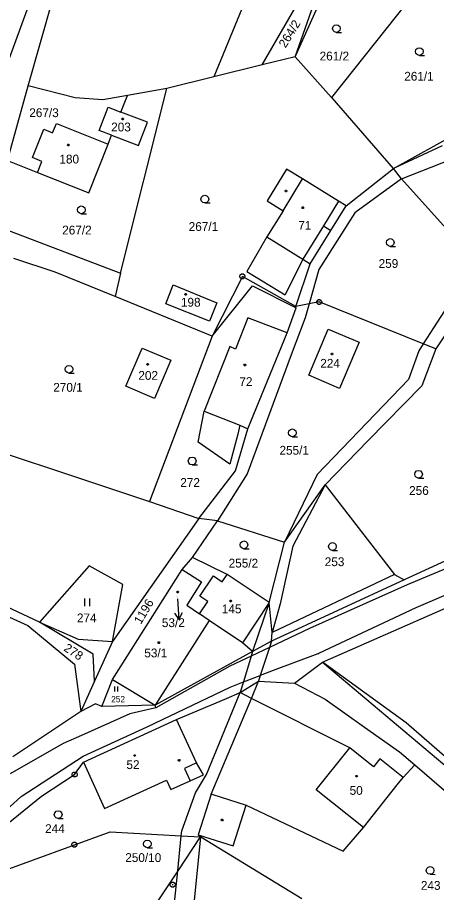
# Model space of a CAD drawing. Extents: x -694465 to -690527, y -983694 to -978978.
# Drawn here: x -692355.9 to -692275, y -981773.5 to -981604.7 of the extents above; entities that cross this region are included whole.
import ezdxf

# ---------------------------------------------------------------- set-up
doc = ezdxf.new("R2010")
doc.units = 0
for name, color, linetype in [('Vrstva 1', 7, 'Continuous'), ('Vrstva 16', 7, 'Continuous'), ('Vrstva 18', 7, 'Continuous'), ('Vrstva 19', 7, 'Continuous'), ('Vrstva 24', 7, 'Continuous'), ('Vrstva 25', 7, 'Continuous'), ('Vrstva 29', 7, 'Continuous')]:
    doc.layers.add(name, color=color, linetype=linetype)

msp = doc.modelspace()

# ---------------------------------------------------------------- linework, layer by layer
at = {"layer": 'Vrstva 1'}
for p, q in [((-692299.625, -981673.727), (-692295.881, -981664.883)), ((-692295.881, -981664.883), (-692289.89, -981667.368)), ((-692289.89, -981667.368), (-692293.694, -981676.29)), ((-692293.694, -981676.29), (-692299.625, -981673.727))]:
    msp.add_line(p, q, dxfattribs=at)
for points in [[(-692307.62, -981590.99), (-692317.93, -981616.19)], [(-692350.11, -981592.51), (-692357.7, -981613.37)], [(-692308.61, -981613.86), (-692298.36, -981596.04)], [(-692302.26, -981612.28), (-692296.79, -981596.72)], [(-692276.27, -981596.23), (-692295.22, -981620.14)], [(-692302.26, -981612.28), (-692297, -981600.55)], [(-692353.77, -981617.9), (-692349.04, -981601.09)], [(-692302.26, -981612.28), (-692308.61, -981613.86)], [(-692295.22, -981620.14), (-692302.26, -981612.28)], [(-692308.61, -981613.86), (-692317.93, -981616.19)], [(-692317.93, -981616.19), (-692327.01, -981618.45)], [(-692357.81, -981632.33), (-692353.77, -981617.9)], [(-692344.71, -981620.23), (-692353.77, -981617.9)], [(-692335.95, -981654.07), (-692327.01, -981618.45)], [(-692327.01, -981618.45), (-692334.63, -981619.78)], [(-692339.36, -981620.61), (-692344.71, -981620.23)], [(-692334.63, -981619.78), (-692339.36, -981620.61)], [(-692335.9, -981622.96), (-692334.63, -981619.78)], [(-692295.12, -981620.24), (-692295.22, -981620.14)], [(-692283.26, -981633.84), (-692295.12, -981620.24)], [(-692340.06, -981626.53), (-692338.34, -981622.02)], [(-692338.34, -981622.02), (-692335.9, -981622.96)], [(-692330.78, -981624.92), (-692335.9, -981622.96)], [(-692349.07, -981626.97), (-692348.35, -981625.19)], [(-692348.35, -981625.19), (-692338.36, -981629.18)], [(-692332.49, -981629.43), (-692330.78, -981624.92)], [(-692352.97, -981631.75), (-692350.78, -981626.28)], [(-692350.78, -981626.28), (-692349.07, -981626.97)], [(-692337.68, -981627.44), (-692340.06, -981626.53)], [(-692338.36, -981629.18), (-692337.68, -981627.44)], [(-692337.68, -981627.44), (-692332.49, -981629.43)], [(-692283.26, -981633.84), (-692270.72, -981626.88)], [(-692342.1, -981638.55), (-692338.36, -981629.18)], [(-692273.88, -981629.46), (-692283.26, -981633.84)], [(-692357.81, -981632.33), (-692351.99, -981634.6)], [(-692351.14, -981632.48), (-692352.97, -981631.75)], [(-692351.99, -981634.6), (-692351.14, -981632.48)], [(-692281.72, -981635.87), (-692272.06, -981632.07)], [(-692351.99, -981634.6), (-692342.1, -981638.55)], [(-692303.9, -981633.95), (-692307.69, -981640.07)], [(-692300.86, -981635.83), (-692303.9, -981633.95)], [(-692292.43, -981641.05), (-692283.26, -981633.84)], [(-692281.72, -981635.87), (-692283.26, -981633.84)], [(-692304.59, -981641.99), (-692300.86, -981635.83)], [(-692293.87, -981640.16), (-692300.86, -981635.83)], [(-692281.72, -981635.87), (-692290.756, -981642.38), (-692297.668, -981653.309), (-692299.571, -981659.973)], [(-692267.3, -981651.89), (-692281.72, -981635.87)], [(-692307.69, -981640.07), (-692304.59, -981641.99)], [(-692293.87, -981640.16), (-692296.81, -981644.9)], [(-692295.36, -981645.79), (-692292.43, -981641.05)], [(-692292.43, -981641.05), (-692293.87, -981640.16)], [(-692304.59, -981641.99), (-692307.73, -981647.06)], [(-692361.21, -981644.47), (-692335.95, -981654.07)], [(-692296.81, -981644.9), (-692300.8, -981651.35)], [(-692299.36, -981652.25), (-692295.36, -981645.79)], [(-692296.81, -981644.9), (-692295.36, -981645.79)], [(-692307.73, -981647.06), (-692311.56, -981653.7)], [(-692307.73, -981647.06), (-692300.8, -981651.35)], [(-692348.56, -981653.87), (-692356.56, -981651.21)], [(-692300.8, -981651.35), (-692304.18, -981658.24)], [(-692300.8, -981651.35), (-692299.36, -981652.25)], [(-692302.1, -981660.47), (-692299.36, -981652.25)], [(-692267.3, -981651.89), (-692277.538, -981667.685)], [(-692336.988, -981658.569), (-692348.56, -981653.87)], [(-692335.95, -981654.07), (-692336.988, -981658.569)], [(-692312.44, -981654.68), (-692318.27, -981666.17)], [(-692302.1, -981660.47), (-692312.44, -981654.68)], [(-692311.56, -981653.7), (-692304.18, -981658.24)], [(-692317.37, -981659.78), (-692318.82, -981663.28), (-692327.25, -981659.96), (-692325.79, -981656.29), (-692317.37, -981659.78)], [(-692318.27, -981666.17), (-692310.52, -981656.5)], [(-692310.52, -981656.5), (-692302.03, -981660.75)], [(-692267.89, -981657.86), (-692275.12, -981668.66)], [(-692318.27, -981666.17), (-692336.988, -981658.569)], [(-692297.62, -981659.59), (-692299.571, -981659.973)], [(-692277.538, -981667.685), (-692297.62, -981659.59)], [(-692299.571, -981659.973), (-692300.343, -981662.678), (-692303.019, -981669.816), (-692311.491, -981692.791), (-692317.25, -981701.8)], [(-692303.82, -981665.56), (-692302.03, -981660.75)], [(-692299.571, -981659.973), (-692302.1, -981660.47)], [(-692302.03, -981660.75), (-692302.1, -981660.47)], [(-692311.4, -981662.69), (-692313.75, -981668.74)], [(-692303.82, -981665.56), (-692311.4, -981662.69)], [(-692318.27, -981666.17), (-692330.39, -981698.13)], [(-692311.38, -981684.08), (-692303.82, -981665.56)], [(-692314.85, -981668.22), (-692319.83, -981680.69)], [(-692313.75, -981668.74), (-692314.85, -981668.22)], [(-692277.538, -981667.685), (-692278.399, -981669.014), (-692280.406, -981674.59), (-692298.019, -981692.881), (-692304.31, -981705.93)], [(-692275.12, -981668.66), (-692277.538, -981667.685)], [(-692326.27, -981670.84), (-692329.39, -981678.21), (-692334.92, -981675.87), (-692331.8, -981668.5), (-692326.27, -981670.84)], [(-692275.12, -981668.66), (-692277.83, -981675.76)], [(-692277.83, -981675.76), (-692288.19, -981686.34)], [(-692320.98, -981686.62), (-692319.83, -981680.69)], [(-692319.83, -981680.69), (-692312.93, -981683.4)], [(-692374.11, -981683.55), (-692330.39, -981698.13)], [(-692312.93, -981683.4), (-692313.32, -981685.08)], [(-692312.93, -981683.4), (-692311.38, -981684.08)], [(-692313.32, -981685.08), (-692314.86, -981690.9)], [(-692313.75, -981692.18), (-692311.38, -981684.08)], [(-692314.86, -981690.9), (-692320.98, -981686.62)], [(-692288.19, -981686.34), (-692296.45, -981694.86)], [(-692320.83, -981701.38), (-692313.75, -981692.18)], [(-692296.45, -981694.86), (-692302.701, -981706.71), (-692305.154, -981717.863)], [(-692304.31, -981705.93), (-692296.45, -981694.86)], [(-692296.45, -981694.86), (-692283.08, -981712.2)], [(-692231.78, -981693.79), (-692280.66, -981714.19)], [(-692330.39, -981698.13), (-692320.83, -981701.38)], [(-692278.89, -981718.56), (-692230.3, -981697.74)], [(-692250.23, -981699), (-692281.2, -981713.23)], [(-692320.83, -981701.38), (-692337.53, -981725.12)], [(-692322.09, -981708.9), (-692317.25, -981701.8)], [(-692317.25, -981701.8), (-692320.83, -981701.38)], [(-692317.25, -981701.8), (-692304.31, -981705.93)], [(-692351.63, -981721.39), (-692384.16, -981706.16)], [(-692307.26, -981717.6), (-692304.31, -981705.93)], [(-692385.08, -981707.85), (-692353.84, -981722.03)], [(-692342.03, -981710.53), (-692351.63, -981721.39)], [(-692335.54, -981714.12), (-692342.03, -981710.53)], [(-692324.1, -981711.25), (-692322.09, -981708.9)], [(-692315.41, -981712.16), (-692322.09, -981708.9)], [(-692337.49, -981732.41), (-692324.1, -981711.25)], [(-692324.1, -981711.25), (-692320.34, -981713.6)], [(-692316.36, -981713.59), (-692315.41, -981712.16)], [(-692307.26, -981717.6), (-692315.41, -981712.16)], [(-692283.08, -981712.2), (-692306.68, -981723.39)], [(-692296.96, -981729.07), (-692257.29, -981711.65)], [(-692283.08, -981712.2), (-692281.2, -981713.23)], [(-692320.34, -981713.6), (-692323.19, -981718.1)], [(-692320.66, -981716.39), (-692318.05, -981712.47)], [(-692318.05, -981712.47), (-692316.36, -981713.59)], [(-692281.2, -981713.23), (-692306.8, -981725.07)], [(-692337.53, -981725.12), (-692335.54, -981714.12)], [(-692280.66, -981714.19), (-692299.48, -981722.62)], [(-692319.14, -981717.41), (-692320.66, -981716.39)], [(-692323.19, -981718.1), (-692320.73, -981719.8)], [(-692320.73, -981719.8), (-692319.14, -981717.41)], [(-692307.26, -981717.6), (-692312.42, -981725.35)], [(-692307.26, -981717.6), (-692310.47, -981727.05)], [(-692306.68, -981723.39), (-692307.26, -981717.6)], [(-692305.154, -981717.863), (-692306.68, -981723.39)], [(-692297.712, -981727.382), (-692278.89, -981718.56)], [(-692318.84, -981721.06), (-692320.73, -981719.8)], [(-692353.84, -981722.03), (-692344.83, -981729.49)], [(-692341.24, -981727.58), (-692351.63, -981721.39)], [(-692351.63, -981721.39), (-692344.16, -981724.65)], [(-692318.84, -981721.06), (-692329.27, -981737.41)], [(-692312.42, -981725.35), (-692318.84, -981721.06)], [(-692299.48, -981722.62), (-692307.19, -981726.25)], [(-692306.8, -981725.07), (-692306.68, -981723.39)], [(-692344.16, -981724.65), (-692337.53, -981725.12)], [(-692337.53, -981725.12), (-692341, -981732.793)], [(-692310.47, -981727.05), (-692312.42, -981725.35)], [(-692306.8, -981725.07), (-692310.47, -981727.05)], [(-692306.8, -981725.07), (-692307.19, -981726.25)], [(-692310.47, -981727.05), (-692329.27, -981737.41)], [(-692307.19, -981726.25), (-692310.74, -981727.92)], [(-692310.47, -981727.05), (-692310.74, -981727.92)], [(-692307.19, -981726.25), (-692308.99, -981731.67)], [(-692297.9, -981727.47), (-692297.712, -981727.382)], [(-692341, -981732.793), (-692341.24, -981727.58)], [(-692310.74, -981727.92), (-692314.85, -981729.86)], [(-692310.74, -981727.92), (-692312.25, -981732.91)], [(-692297.9, -981727.47), (-692306.477, -981730.718)], [(-692302.4, -981733.16), (-692296.96, -981729.07)], [(-692280.84, -981740.82), (-692296.96, -981729.07)], [(-692296.96, -981729.07), (-692262.73, -981757.9)], [(-692344.83, -981729.49), (-692343.64, -981738.63)], [(-692314.85, -981729.86), (-692329.14, -981737.9)], [(-692306.477, -981730.718), (-692308.99, -981731.67)], [(-692339.6, -981737.65), (-692337.49, -981732.41)], [(-692337.49, -981732.41), (-692329.27, -981737.41)], [(-692312.25, -981732.91), (-692308.99, -981731.67)], [(-692308.99, -981731.67), (-692309.35, -981732.74)], [(-692341, -981732.793), (-692343.64, -981738.63)], [(-692330.85, -981741.55), (-692314.82, -981733.95)], [(-692314.82, -981733.95), (-692312.25, -981732.91)], [(-692312.88, -981734.97), (-692309.35, -981732.74)], [(-692312.25, -981732.91), (-692312.85, -981734.872)], [(-692310.664, -981736.084), (-692309.35, -981732.74)], [(-692309.35, -981732.74), (-692302.4, -981733.16)], [(-692302.4, -981733.16), (-692296.44, -981736.23)], [(-692321.492, -981754.275), (-692319.349, -981750.77), (-692312.892, -981734.975)], [(-692315.519, -981736.085), (-692312.892, -981734.975)], [(-692312.892, -981734.975), (-692312.85, -981734.872)], [(-692312.892, -981734.975), (-692312.88, -981734.97)], [(-692312.85, -981734.872), (-692312.88, -981734.97)], [(-692310.664, -981736.084), (-692312.88, -981734.97)], [(-692340.8, -981737.15), (-692343.64, -981738.63)], [(-692339.6, -981737.65), (-692340.8, -981737.15)], [(-692329.27, -981737.41), (-692339.6, -981737.65)], [(-692329.14, -981737.9), (-692329.27, -981737.41)], [(-692325.14, -981740.15), (-692315.519, -981736.085)], [(-692318.49, -981754.54), (-692310.664, -981736.084)], [(-692291.72, -981745.61), (-692310.664, -981736.084)], [(-692296.44, -981736.23), (-692288.84, -981741.61)], [(-692343.64, -981738.63), (-692356.757, -981747.363)], [(-692334.2, -981739.06), (-692343.508, -981743.218)], [(-692329.14, -981737.9), (-692334.2, -981739.06)], [(-692343.14, -981748.4), (-692325.14, -981740.15)], [(-692321.29, -981748.55), (-692325.14, -981740.15)], [(-692262.05, -981757.15), (-692280.84, -981740.82)], [(-692343.21, -981747.24), (-692330.85, -981741.55)], [(-692288.84, -981741.61), (-692282.09, -981746.39)], [(-692343.508, -981743.218), (-692347.05, -981744.8)], [(-692347.05, -981744.8), (-692357.25, -981750.65)], [(-692298.19, -981753.74), (-692291.72, -981745.61)], [(-692287.13, -981749.27), (-692291.72, -981745.61)], [(-692355.16, -981755.04), (-692343.21, -981747.24)], [(-692282.09, -981746.39), (-692279.142, -981748.931)], [(-692344.83, -981750.77), (-692343.14, -981748.4)], [(-692343.14, -981748.4), (-692339.05, -981757.32)], [(-692321.29, -981748.55), (-692323.62, -981749.62)], [(-692319.97, -981750.86), (-692321.29, -981748.55)], [(-692285.93, -981747.76), (-692287.13, -981749.27)], [(-692281.41, -981751.35), (-692285.93, -981747.76)], [(-692281.41, -981751.35), (-692279.142, -981748.931)], [(-692279.142, -981748.931), (-692251.02, -981773.17)], [(-692351.21, -981754.97), (-692344.83, -981750.77)], [(-692323.62, -981749.62), (-692322.54, -981751.98)], [(-692322.54, -981751.98), (-692319.97, -981750.86)], [(-692339.05, -981757.32), (-692327.09, -981751.84)], [(-692327.09, -981751.84), (-692326.25, -981753.68)], [(-692326.25, -981753.68), (-692322.54, -981751.98)], [(-692289.09, -981760.99), (-692282.55, -981752.77)], [(-692282.55, -981752.77), (-692281.41, -981751.35)], [(-692324.244, -981762.589), (-692324.149, -981761.636), (-692321.492, -981754.275)], [(-692289.09, -981760.99), (-692298.19, -981753.74)], [(-692368.2, -981766.86), (-692355.16, -981755.04)], [(-692363.57, -981764.94), (-692351.21, -981754.97)], [(-692318.49, -981754.54), (-692320.99, -981762.38)], [(-692318.49, -981754.54), (-692318.36, -981754.581)], [(-692318.36, -981754.581), (-692311.74, -981756.69)], [(-692314.24, -981764.53), (-692311.74, -981756.69)], [(-692311.74, -981756.69), (-692293, -981765.54)], [(-692293, -981765.54), (-692289.09, -981760.99)], [(-692360.24, -981769.91), (-692337.99, -981761.8)], [(-692337.99, -981761.8), (-692324.244, -981762.589)], [(-692324.917, -981769.33), (-692324.244, -981762.589)], [(-692320.57, -981762.8), (-692324.917, -981769.33)], [(-692324.244, -981762.589), (-692320.57, -981762.8)], [(-692322.887, -981788.725), (-692323.034, -981788.549), (-692320.494, -981762.846)], [(-692320.57, -981762.8), (-692320.99, -981762.38)], [(-692320.99, -981762.38), (-692314.24, -981764.53)], [(-692320.494, -981762.846), (-692320.57, -981762.8)], [(-692300.94, -981774.75), (-692320.494, -981762.846)], [(-692324.917, -981769.33), (-692352.355, -981810.441)], [(-692326.9, -981788.4), (-692324.917, -981769.33)]]:
    msp.add_lwpolyline(points, dxfattribs=at)
at = {"layer": 'Vrstva 24'}
for points in [[(-692312.286, -981654.204), (-692312.036, -981654.386), (-692311.94, -981654.68), (-692312.036, -981654.974), (-692312.286, -981655.156), (-692312.594, -981655.156), (-692312.844, -981654.974), (-692312.94, -981654.68), (-692312.844, -981654.386), (-692312.594, -981654.204)], [(-692297.466, -981659.114), (-692297.216, -981659.296), (-692297.12, -981659.59), (-692297.216, -981659.884), (-692297.466, -981660.066), (-692297.774, -981660.066), (-692298.024, -981659.884), (-692298.12, -981659.59), (-692298.024, -981659.296), (-692297.774, -981659.114)], [(-692344.676, -981750.294), (-692344.426, -981750.476), (-692344.33, -981750.77), (-692344.426, -981751.064), (-692344.676, -981751.246), (-692344.984, -981751.246), (-692345.234, -981751.064), (-692345.33, -981750.77), (-692345.234, -981750.476), (-692344.984, -981750.294)], [(-692344.726, -981763.834), (-692344.476, -981764.016), (-692344.38, -981764.31), (-692344.476, -981764.604), (-692344.726, -981764.786), (-692345.034, -981764.786), (-692345.284, -981764.604), (-692345.38, -981764.31), (-692345.284, -981764.016), (-692345.034, -981763.834)], [(-692325.756, -981771.534), (-692325.506, -981771.716), (-692325.41, -981772.01), (-692325.506, -981772.304), (-692325.756, -981772.486), (-692326.064, -981772.486), (-692326.314, -981772.304), (-692326.41, -981772.01), (-692326.314, -981771.716), (-692326.064, -981771.534)]]:
    msp.add_lwpolyline(points, close=True, dxfattribs=at)
for points in [[(-692312.559, -981654.68), (-692312.32, -981654.68)], [(-692297.739, -981659.59), (-692297.5, -981659.59)], [(-692344.949, -981750.77), (-692344.71, -981750.77)], [(-692344.999, -981764.31), (-692344.76, -981764.31)], [(-692326.029, -981772.01), (-692325.79, -981772.01)]]:
    msp.add_lwpolyline(points, dxfattribs=at)
at = {"layer": 'Vrstva 25'}
for points in [[(-692294.3, -981607.61), (-692294.675, -981607.509), (-692294.949, -981607.235), (-692295.05, -981606.86), (-692294.949, -981606.485), (-692294.675, -981606.211), (-692294.3, -981606.11), (-692293.925, -981606.211), (-692293.651, -981606.485), (-692293.55, -981606.86), (-692293.651, -981607.235), (-692293.925, -981607.509), (-692294.3, -981607.61), (-692293.3, -981607.611)], [(-692278.28, -981612.05), (-692278.655, -981611.949), (-692278.929, -981611.675), (-692279.03, -981611.3), (-692278.929, -981610.925), (-692278.655, -981610.651), (-692278.28, -981610.55), (-692277.905, -981610.651), (-692277.631, -981610.925), (-692277.53, -981611.3), (-692277.631, -981611.675), (-692277.905, -981611.949), (-692278.28, -981612.05), (-692277.28, -981612.051)], [(-692319.69, -981640.5), (-692320.065, -981640.399), (-692320.339, -981640.125), (-692320.44, -981639.75), (-692320.339, -981639.375), (-692320.065, -981639.101), (-692319.69, -981639), (-692319.315, -981639.101), (-692319.041, -981639.375), (-692318.94, -981639.75), (-692319.041, -981640.125), (-692319.315, -981640.399), (-692319.69, -981640.5), (-692318.69, -981640.501)], [(-692343.54, -981642.58), (-692343.915, -981642.479), (-692344.189, -981642.205), (-692344.29, -981641.83), (-692344.189, -981641.455), (-692343.915, -981641.181), (-692343.54, -981641.08), (-692343.165, -981641.181), (-692342.891, -981641.455), (-692342.79, -981641.83), (-692342.891, -981642.205), (-692343.165, -981642.479), (-692343.54, -981642.58), (-692342.54, -981642.581)], [(-692283.89, -981648.87), (-692284.265, -981648.769), (-692284.539, -981648.495), (-692284.64, -981648.12), (-692284.539, -981647.745), (-692284.265, -981647.471), (-692283.89, -981647.37), (-692283.515, -981647.471), (-692283.241, -981647.745), (-692283.14, -981648.12), (-692283.241, -981648.495), (-692283.515, -981648.769), (-692283.89, -981648.87), (-692282.89, -981648.871)], [(-692345.92, -981673.34), (-692346.295, -981673.239), (-692346.569, -981672.965), (-692346.67, -981672.59), (-692346.569, -981672.215), (-692346.295, -981671.941), (-692345.92, -981671.84), (-692345.545, -981671.941), (-692345.271, -981672.215), (-692345.17, -981672.59), (-692345.271, -981672.965), (-692345.545, -981673.239), (-692345.92, -981673.34), (-692344.92, -981673.341)], [(-692302.8, -981685.6), (-692303.175, -981685.499), (-692303.449, -981685.225), (-692303.55, -981684.85), (-692303.449, -981684.475), (-692303.175, -981684.201), (-692302.8, -981684.1), (-692302.425, -981684.201), (-692302.151, -981684.475), (-692302.05, -981684.85), (-692302.151, -981685.225), (-692302.425, -981685.499), (-692302.8, -981685.6), (-692301.8, -981685.601)], [(-692322.14, -981691.03), (-692322.515, -981690.929), (-692322.789, -981690.655), (-692322.89, -981690.28), (-692322.789, -981689.905), (-692322.515, -981689.631), (-692322.14, -981689.53), (-692321.765, -981689.631), (-692321.491, -981689.905), (-692321.39, -981690.28), (-692321.491, -981690.655), (-692321.765, -981690.929), (-692322.14, -981691.03), (-692321.14, -981691.031)], [(-692278.43, -981693.6), (-692278.805, -981693.499), (-692279.079, -981693.225), (-692279.18, -981692.85), (-692279.079, -981692.475), (-692278.805, -981692.201), (-692278.43, -981692.1), (-692278.055, -981692.201), (-692277.781, -981692.475), (-692277.68, -981692.85), (-692277.781, -981693.225), (-692278.055, -981693.499), (-692278.43, -981693.6), (-692277.43, -981693.601)], [(-692312.14, -981707.22), (-692312.515, -981707.119), (-692312.789, -981706.845), (-692312.89, -981706.47), (-692312.789, -981706.095), (-692312.515, -981705.821), (-692312.14, -981705.72), (-692311.765, -981705.821), (-692311.491, -981706.095), (-692311.39, -981706.47), (-692311.491, -981706.845), (-692311.765, -981707.119), (-692312.14, -981707.22), (-692311.14, -981707.221)], [(-692295.06, -981707.54), (-692295.435, -981707.439), (-692295.709, -981707.165), (-692295.81, -981706.79), (-692295.709, -981706.415), (-692295.435, -981706.141), (-692295.06, -981706.04), (-692294.685, -981706.141), (-692294.411, -981706.415), (-692294.31, -981706.79), (-692294.411, -981707.165), (-692294.685, -981707.439), (-692295.06, -981707.54), (-692294.06, -981707.541)], [(-692342.9, -981716.82), (-692342.9, -981718.32)], [(-692341.9, -981718.32), (-692341.9, -981716.82)], [(-692337.145, -981733.775), (-692337.145, -981734.78)], [(-692336.475, -981734.78), (-692336.475, -981733.775)], [(-692348.01, -981759.26), (-692348.385, -981759.159), (-692348.659, -981758.885), (-692348.76, -981758.51), (-692348.659, -981758.135), (-692348.385, -981757.861), (-692348.01, -981757.76), (-692347.635, -981757.861), (-692347.361, -981758.135), (-692347.26, -981758.51), (-692347.361, -981758.885), (-692347.635, -981759.159), (-692348.01, -981759.26), (-692347.01, -981759.261)], [(-692330.79, -981764.92), (-692331.165, -981764.819), (-692331.439, -981764.545), (-692331.54, -981764.17), (-692331.439, -981763.795), (-692331.165, -981763.521), (-692330.79, -981763.42), (-692330.415, -981763.521), (-692330.141, -981763.795), (-692330.04, -981764.17), (-692330.141, -981764.545), (-692330.415, -981764.819), (-692330.79, -981764.92), (-692329.79, -981764.921)], [(-692276.21, -981770.03), (-692276.585, -981769.929), (-692276.859, -981769.655), (-692276.96, -981769.28), (-692276.859, -981768.905), (-692276.585, -981768.631), (-692276.21, -981768.53), (-692275.835, -981768.631), (-692275.561, -981768.905), (-692275.46, -981769.28), (-692275.561, -981769.655), (-692275.835, -981769.929), (-692276.21, -981770.03), (-692275.21, -981770.031)]]:
    msp.add_lwpolyline(points, dxfattribs=at)
for points in [[(-692335.483, -981624.158), (-692335.395, -981624.31), (-692335.483, -981624.462), (-692335.657, -981624.462), (-692335.745, -981624.31), (-692335.657, -981624.158)], [(-692345.963, -981629.188), (-692345.875, -981629.34), (-692345.963, -981629.492), (-692346.137, -981629.492), (-692346.225, -981629.34), (-692346.137, -981629.188)], [(-692303.923, -981638.028), (-692303.835, -981638.18), (-692303.923, -981638.332), (-692304.097, -981638.332), (-692304.185, -981638.18), (-692304.097, -981638.028)], [(-692300.693, -981641.248), (-692300.605, -981641.4), (-692300.693, -981641.552), (-692300.867, -981641.552), (-692300.955, -981641.4), (-692300.867, -981641.248)], [(-692323.313, -981657.958), (-692323.225, -981658.11), (-692323.313, -981658.262), (-692323.487, -981658.262), (-692323.575, -981658.11), (-692323.487, -981657.958)], [(-692295.053, -981669.468), (-692294.965, -981669.62), (-692295.053, -981669.772), (-692295.227, -981669.772), (-692295.315, -981669.62), (-692295.227, -981669.468)], [(-692330.653, -981671.468), (-692330.565, -981671.62), (-692330.653, -981671.772), (-692330.827, -981671.772), (-692330.915, -981671.62), (-692330.827, -981671.468)], [(-692311.873, -981671.628), (-692311.785, -981671.78), (-692311.873, -981671.932), (-692312.047, -981671.932), (-692312.135, -981671.78), (-692312.047, -981671.628)], [(-692324.833, -981715.408), (-692324.745, -981715.56), (-692324.833, -981715.712), (-692325.007, -981715.712), (-692325.095, -981715.56), (-692325.007, -981715.408)], [(-692314.633, -981717.158), (-692314.545, -981717.31), (-692314.633, -981717.462), (-692314.807, -981717.462), (-692314.895, -981717.31), (-692314.807, -981717.158)], [(-692328.483, -981725.198), (-692328.395, -981725.35), (-692328.483, -981725.502), (-692328.657, -981725.502), (-692328.745, -981725.35), (-692328.657, -981725.198)], [(-692333.153, -981746.958), (-692333.065, -981747.11), (-692333.153, -981747.262), (-692333.327, -981747.262), (-692333.415, -981747.11), (-692333.327, -981746.958)], [(-692324.573, -981747.888), (-692324.485, -981748.04), (-692324.573, -981748.192), (-692324.747, -981748.192), (-692324.835, -981748.04), (-692324.747, -981747.888)], [(-692290.313, -981750.938), (-692290.225, -981751.09), (-692290.313, -981751.242), (-692290.487, -981751.242), (-692290.575, -981751.09), (-692290.487, -981750.938)], [(-692316.273, -981759.378), (-692316.185, -981759.53), (-692316.273, -981759.682), (-692316.447, -981759.682), (-692316.535, -981759.53), (-692316.447, -981759.378)]]:
    msp.add_lwpolyline(points, close=True, dxfattribs=at)
at = {"layer": 'Vrstva 29'}
for points in [[(-692324.98, -981716.89), (-692324.683, -981720.879), (-692324.031, -981719.527)], [(-692325.527, -981719.638), (-692324.683, -981720.879)]]:
    msp.add_lwpolyline(points, dxfattribs=at)

# ---------------------------------------------------------------- texts
at = {"layer": 'Vrstva 16'}
msp.add_text('53/2', height=1.7, dxfattribs=at).set_placement((-692327.985, -981722.33))
at = {"layer": 'Vrstva 18'}
for s, rotation, p in [('264/2', 58.49899, (-692304.106, -981610.708)), ('1196', 59.41572, (-692332.04, -981721.912)), ('278', 326.70054, (-692347.078, -981726.768))]:
    msp.add_text(s, height=1.7, rotation=rotation, dxfattribs=at).set_placement(p)
for s, height, p in [('261/2', 1.7, (-692297.532, -981613.01)), ('261/1', 1.7, (-692281.201, -981616.91)), ('267/3', 1.7, (-692353.584, -981623.94)), ('267/1', 1.7, (-692322.809, -981645.9)), ('267/2', 1.7, (-692347.23, -981646.58)), ('259', 1.7, (-692286.143, -981653.03)), ('270/1', 1.7, (-692348.955, -981676.93)), ('255/1', 1.7, (-692305.283, -981689.07)), ('272', 1.7, (-692324.431, -981695.28)), ('256', 1.7, (-692280.255, -981696.83)), ('253', 1.7, (-692296.542, -981710.57)), ('255/2', 1.7, (-692315.094, -981710.84)), ('274', 1.7, (-692344.388, -981721.41)), ('252', 1.2, (-692337.772, -981736.83)), ('244', 1.7, (-692350.528, -981762.07)), ('250/10', 1.7, (-692335.058, -981767.65)), ('243', 1.7, (-692277.985, -981773.02))]:
    msp.add_text(s, height=height, dxfattribs=at).set_placement(p)
at = {"layer": 'Vrstva 19'}
for s, height, p in [('203', 1.7, (-692337.773, -981626.7)), ('180', 1.7, (-692347.77, -981632.89)), ('71', 1.7, (-692301.657, -981645.67)), ('198', 1.7, (-692324.307, -981660.51)), ('224', 1.7, (-692297.411, -981672.29)), ('202', 1.7, (-692332.523, -981674.62)), ('72', 1.7, (-692313.028, -981675.82)), ('53/2', 0.1, (-692325.174, -981716.56)), ('145', 1.7, (-692316.413, -981719.67)), ('53/1', 1.7, (-692331.38, -981728.17)), ('52', 1.7, (-692334.835, -981749.72)), ('50', 1.7, (-692291.739, -981754.69))]:
    msp.add_text(s, height=height, dxfattribs=at).set_placement(p)

doc.saveas('drawing.dxf')
